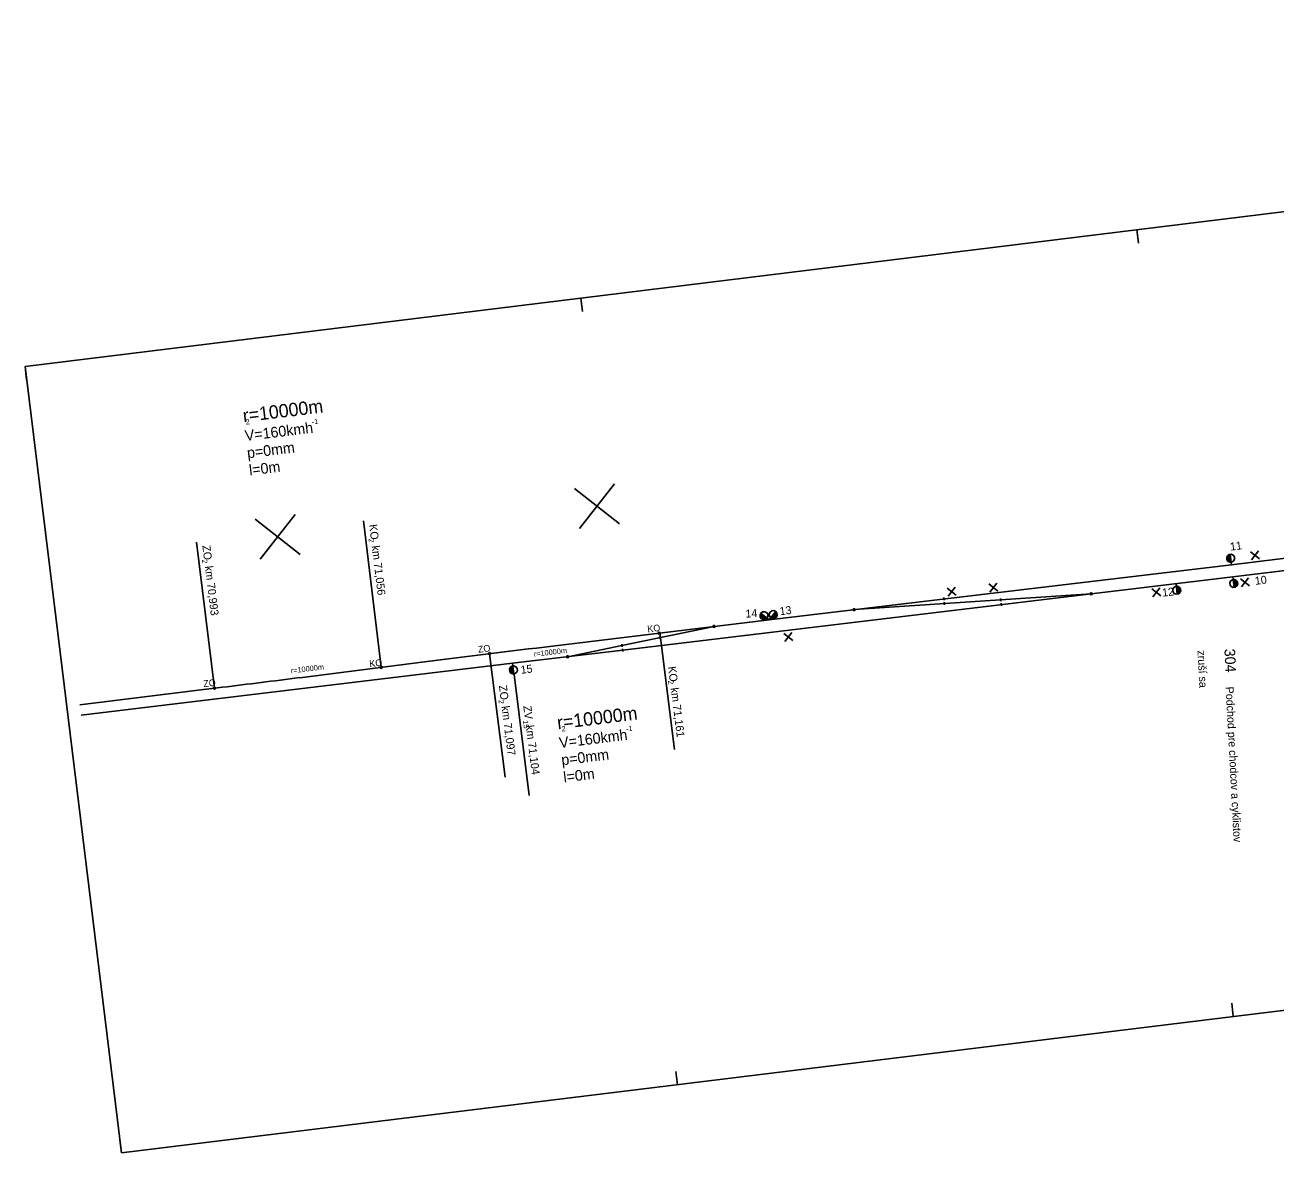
# Model space of a CAD drawing. Extents: x -559083 to -556962, y -1276579 to -1276028.
# Drawn here: x -559082.8 to -558613.7, y -1276578.6 to -1276155.9 of the extents above; entities that cross this region are included whole.
import ezdxf

# ---------------------------------------------------------------- set-up
doc = ezdxf.new("R2010")
doc.units = 0
for name, color, linetype in [('kolaj s', 7, 'Continuous'), ('popis 25', 7, 'Continuous'), ('popis 50', 7, 'Continuous'), ('ram vykresu', 7, 'Continuous'), ('stavby', 7, 'Continuous')]:
    doc.layers.add(name, color=color, linetype=linetype)

msp = doc.modelspace()

# ---------------------------------------------------------------- linework, layer by layer
at = {"layer": 'kolaj s'}
for p, q in [((-558630.38, -1276358.2), (-558589.1, -1276353.13)), ((-558630.38, -1276358.2), (-558727.08, -1276369.68)), ((-558629.83, -1276362.72), (-558588.54, -1276357.65)), ((-558858.64, -1276390.16), (-558629.83, -1276362.72)), ((-558727.08, -1276369.68), (-558803.72, -1276378.77)), ((-558771.92, -1276375), (-558682.98, -1276369.05)), ((-558738.22, -1276370.5), (-558738.1, -1276371.49)), ((-558738.16, -1276370.99), (-558738.16, -1276370.99)), ((-558716.97, -1276370.81), (-558716.84, -1276371.81)), ((-558682.98, -1276369.05), (-558682.98, -1276369.05)), ((-558771.92, -1276375), (-558771.92, -1276375)), ((-558738.06, -1276372.23), (-558737.94, -1276373.23)), ((-558738, -1276372.73), (-558738, -1276372.73)), ((-558716.91, -1276371.31), (-558716.91, -1276371.31)), ((-558716.79, -1276372.61), (-558716.67, -1276373.61)), ((-558716.73, -1276373.11), (-558716.73, -1276373.11)), ((-558803.72, -1276378.77), (-558885.02, -1276388.64)), ((-558824.36, -1276381.27), (-558858.92, -1276388.45)), ((-558844.95, -1276384.28), (-558845.07, -1276383.28)), ((-558845.02, -1276383.78), (-558845.02, -1276383.78)), ((-558845.01, -1276383.78), (-558845.01, -1276383.78)), ((-558844.63, -1276385.98), (-558844.83, -1276385)), ((-558824.36, -1276381.27), (-558824.36, -1276381.27)), ((-558879.29, -1276392.63), (-558858.92, -1276388.45)), ((-558859.02, -1276387.96), (-558858.82, -1276388.94)), ((-558858.92, -1276388.45), (-558858.92, -1276388.45)), ((-558858.7, -1276389.66), (-558858.58, -1276390.66)), ((-558844.73, -1276385.49), (-558844.73, -1276385.49)), ((-558979.74, -1276400.49), (-558932.96, -1276394.57)), ((-558908.55, -1276391.49), (-558908.55, -1276391.49)), ((-558899.94, -1276395.11), (-558858.64, -1276390.16)), ((-558879.29, -1276392.63), (-558879.29, -1276392.63)), ((-558858.64, -1276390.16), (-558858.64, -1276390.16)), ((-559061.68, -1276414.58), (-558899.94, -1276395.11)), ((-558949.2, -1276396.63), (-558949.2, -1276396.63)), ((-559008.73, -1276404.1), (-559062.16, -1276410.62)), ((-559011.74, -1276404.41), (-559011.74, -1276404.41))]:
    msp.add_line(p, q, dxfattribs=at)
for points in [[(-558682.98, -1276369.46), (-558683.32, -1276369.26), (-558683.32, -1276368.86), (-558682.98, -1276368.66), (-558682.63, -1276368.86), (-558682.63, -1276369.26), (-558682.98, -1276369.46)], [(-558771.52, -1276375), (-558771.71, -1276375.34), (-558772.11, -1276375.34), (-558772.32, -1276375), (-558772.11, -1276374.65), (-558771.71, -1276374.65), (-558771.52, -1276375)], [(-558844.97, -1276384.18), (-558845.33, -1276384.02), (-558845.38, -1276383.62), (-558845.06, -1276383.38), (-558844.69, -1276383.54), (-558844.65, -1276383.94), (-558844.97, -1276384.18)], [(-558824.76, -1276381.32), (-558824.6, -1276380.96), (-558824.21, -1276380.91), (-558823.96, -1276381.23), (-558824.12, -1276381.59), (-558824.52, -1276381.64), (-558824.76, -1276381.32)], [(-558908.6, -1276391.09), (-558908.23, -1276391.25), (-558908.18, -1276391.65), (-558908.5, -1276391.89), (-558908.87, -1276391.73), (-558908.92, -1276391.34), (-558908.6, -1276391.09)], [(-558878.89, -1276392.59), (-558879.05, -1276392.95), (-558879.44, -1276393), (-558879.68, -1276392.68), (-558879.53, -1276392.31), (-558879.13, -1276392.27), (-558878.89, -1276392.59)], [(-558949.25, -1276396.24), (-558948.88, -1276396.39), (-558948.83, -1276396.79), (-558949.15, -1276397.03), (-558949.52, -1276396.87), (-558949.57, -1276396.48), (-558949.25, -1276396.24)], [(-559011.79, -1276404.02), (-559011.42, -1276404.17), (-559011.37, -1276404.57), (-559011.69, -1276404.81), (-559012.06, -1276404.65), (-559012.11, -1276404.26), (-559011.79, -1276404.02)]]:
    msp.add_lwpolyline(points, dxfattribs=at)
for centre, start, end in [((-557680.08, -1286315.78), 96.920597, 97.197383), ((-560233.25, -1266479.36), 277.033672, 277.20105)]:
    msp.add_arc(centre, 10000, start, end, dxfattribs=at)
at = {"layer": 'popis 50'}
for p, q in [((-558861.67, -1276327.78), (-558874.83, -1276344.62)), ((-558859.83, -1276342.78), (-558876.68, -1276329.62)), ((-558979.59, -1276354.28), (-558996.44, -1276341.12)), ((-558981.44, -1276339.28), (-558994.59, -1276356.12)), ((-558955.89, -1276341.73), (-558949.21, -1276396.58)), ((-559018.41, -1276349.65), (-559011.73, -1276404.43)), ((-558630.38, -1276358.2), (-558630.86, -1276354.28)), ((-558619.88, -1276355.9), (-558623.25, -1276353.27)), ((-558620.25, -1276352.9), (-558622.88, -1276356.27)), ((-558630.38, -1276358.2), (-558630.38, -1276358.2)), ((-558718.04, -1276368.01), (-558721.41, -1276365.38)), ((-558718.41, -1276365.01), (-558721.04, -1276368.38)), ((-558651.18, -1276365.23), (-558651.18, -1276365.23)), ((-558651.18, -1276365.23), (-558650.7, -1276369.15)), ((-558629.83, -1276362.72), (-558629.83, -1276362.72)), ((-558629.83, -1276362.72), (-558629.35, -1276366.64)), ((-558623.57, -1276366.07), (-558626.94, -1276363.44)), ((-558623.94, -1276363.07), (-558626.57, -1276366.44)), ((-558733.6, -1276369.6), (-558736.97, -1276366.97)), ((-558733.97, -1276366.6), (-558736.6, -1276369.97)), ((-558656.93, -1276369.78), (-558660.3, -1276367.14)), ((-558657.3, -1276366.78), (-558659.93, -1276370.14)), ((-558803.72, -1276378.77), (-558803.72, -1276378.77)), ((-558839.22, -1276427.47), (-558844.76, -1276383.62)), ((-558794.89, -1276386.61), (-558798.26, -1276383.98)), ((-558795.26, -1276383.61), (-558797.89, -1276386.98)), ((-558902.72, -1276437.72), (-558908.55, -1276391.58)), ((-558899.94, -1276395.11), (-558899.94, -1276395.11)), ((-558899.94, -1276395.11), (-558899.45, -1276399.03)), ((-558893.67, -1276444.64), (-558899.4, -1276399.25))]:
    msp.add_line(p, q, dxfattribs=at)
for points in [[(-558631.26, -1276354.32), (-558630.47, -1276354.23), (-558629.74, -1276354.55), (-558629.3, -1276355.15), (-558629.2, -1276355.92), (-558629.51, -1276356.64), (-558630.11, -1276357.11), (-558630.91, -1276357.2), (-558631.61, -1276356.9), (-558632.08, -1276356.29), (-558632.18, -1276355.5), (-558631.87, -1276354.79), (-558631.26, -1276354.32), (-558631.48, -1276354.6), (-558630.98, -1276354.54), (-558630.95, -1276354.84), (-558631.79, -1276354.94), (-558631.95, -1276355.27), (-558630.91, -1276355.14), (-558630.87, -1276355.44), (-558632.02, -1276355.58), (-558631.98, -1276355.87), (-558630.84, -1276355.73), (-558630.8, -1276356.03), (-558631.94, -1276356.17), (-558631.76, -1276356.45), (-558630.76, -1276356.33), (-558630.73, -1276356.63), (-558631.57, -1276356.73), (-558631.19, -1276356.99), (-558630.69, -1276356.93)], [(-558650.3, -1276369.1), (-558651.1, -1276369.2), (-558651.82, -1276368.88), (-558652.27, -1276368.29), (-558652.36, -1276367.49), (-558652.06, -1276366.79), (-558651.45, -1276366.32), (-558650.66, -1276366.23), (-558649.95, -1276366.53), (-558649.48, -1276367.15), (-558649.39, -1276367.92), (-558649.69, -1276368.64), (-558650.3, -1276369.1), (-558650.08, -1276368.83), (-558650.58, -1276368.89), (-558650.62, -1276368.59), (-558649.77, -1276368.49), (-558649.66, -1276368.17), (-558650.65, -1276368.29), (-558650.69, -1276367.99), (-558649.55, -1276367.85), (-558649.58, -1276367.56), (-558650.73, -1276367.7), (-558650.76, -1276367.4), (-558649.62, -1276367.26), (-558649.81, -1276366.98), (-558650.8, -1276367.1), (-558650.84, -1276366.8), (-558650.04, -1276366.71), (-558650.43, -1276366.45), (-558650.87, -1276366.51)], [(-558628.95, -1276366.59), (-558629.74, -1276366.69), (-558630.47, -1276366.37), (-558630.91, -1276365.78), (-558631.01, -1276364.98), (-558630.71, -1276364.28), (-558630.1, -1276363.81), (-558629.3, -1276363.71), (-558628.6, -1276364.02), (-558628.13, -1276364.64), (-558628.04, -1276365.41), (-558628.34, -1276366.12), (-558628.95, -1276366.59), (-558628.73, -1276366.31), (-558629.23, -1276366.37), (-558629.27, -1276366.08), (-558628.42, -1276365.97), (-558628.31, -1276365.66), (-558629.3, -1276365.78), (-558629.34, -1276365.48), (-558628.2, -1276365.34), (-558628.23, -1276365.04), (-558629.37, -1276365.18), (-558629.41, -1276364.89), (-558628.27, -1276364.75), (-558628.45, -1276364.47), (-558629.45, -1276364.59), (-558629.48, -1276364.29), (-558628.69, -1276364.19), (-558629.07, -1276363.94), (-558629.52, -1276363.99)], [(-558804.49, -1276378.17), (-558804.18, -1276377.46), (-558804.28, -1276376.69), (-558804.74, -1276376.06), (-558805.46, -1276375.76), (-558806.23, -1276375.85), (-558806.85, -1276376.32), (-558807.16, -1276377.04), (-558807.06, -1276377.81), (-558806.59, -1276378.43), (-558805.88, -1276378.73), (-558805.11, -1276378.64), (-558804.49, -1276378.17), (-558804.86, -1276378.05), (-558805.26, -1276378.56), (-558805.65, -1276378.6), (-558805.13, -1276377.94), (-558805.36, -1276377.71), (-558805.96, -1276378.54), (-558806.28, -1276378.43), (-558805.58, -1276377.54), (-558805.81, -1276377.36), (-558806.55, -1276378.26), (-558806.73, -1276378.03), (-558806.04, -1276377.14), (-558806.26, -1276376.97), (-558806.87, -1276377.75), (-558806.97, -1276377.35), (-558806.53, -1276376.8), (-558806.76, -1276376.57), (-558806.98, -1276376.85)], [(-558806.84, -1276376.33), (-558803.72, -1276378.77), (-558801.28, -1276375.65)], [(-558801.27, -1276375.64), (-558801.99, -1276375.33), (-558802.76, -1276375.43), (-558803.41, -1276375.93), (-558803.68, -1276376.61), (-558803.59, -1276377.38), (-558803.12, -1276378), (-558802.4, -1276378.3), (-558801.63, -1276378.21), (-558801.04, -1276377.78), (-558800.71, -1276377.03), (-558800.8, -1276376.26), (-558801.27, -1276375.64), (-558801.34, -1276376.01), (-558800.95, -1276376.31), (-558800.89, -1276376.76), (-558801.51, -1276376.28), (-558801.68, -1276376.51), (-558800.9, -1276377.11), (-558801.01, -1276377.43), (-558801.9, -1276376.73), (-558802.07, -1276377.01), (-558801.19, -1276377.65), (-558801.41, -1276377.88), (-558802.25, -1276377.23), (-558802.42, -1276377.45), (-558801.64, -1276378.06), (-558802.09, -1276378.12), (-558802.64, -1276377.68), (-558802.82, -1276377.9), (-558802.48, -1276378.17)], [(-558899.85, -1276399.08), (-558899.06, -1276398.98), (-558898.45, -1276398.51), (-558898.14, -1276397.81), (-558898.24, -1276397.02), (-558898.71, -1276396.41), (-558899.45, -1276396.1), (-558900.19, -1276396.2), (-558900.81, -1276396.67), (-558901.12, -1276397.37), (-558901.02, -1276398.16), (-558900.56, -1276398.77), (-558899.85, -1276399.08), (-558900.13, -1276398.86), (-558899.63, -1276398.8), (-558899.67, -1276398.5), (-558900.51, -1276398.6), (-558900.75, -1276398.33), (-558899.71, -1276398.2), (-558899.74, -1276397.9), (-558900.89, -1276398.04), (-558900.92, -1276397.75), (-558899.78, -1276397.61), (-558899.82, -1276397.31), (-558900.96, -1276397.45), (-558900.85, -1276397.13), (-558899.85, -1276397.01), (-558899.89, -1276396.71), (-558900.73, -1276396.82), (-558900.37, -1276396.47), (-558899.93, -1276396.42)]]:
    msp.add_lwpolyline(points, dxfattribs=at)
at = {"layer": 'ram vykresu'}
for p, q in [((-559082.77, -1276283.84), (-558040.59, -1276155.88)), ((-558665.29, -1276237.62), (-558665.9, -1276232.66)), ((-558873.72, -1276263.21), (-558874.33, -1276258.25)), ((-559046.57, -1276578.63), (-559082.77, -1276283.84)), ((-559082.16, -1276288.8), (-559082.77, -1276283.84)), ((-558004.4, -1276450.67), (-559046.57, -1276578.63)), ((-558629.7, -1276527.44), (-558630.31, -1276522.48)), ((-558838.14, -1276553.04), (-558838.75, -1276548.07)), ((-559046.57, -1276578.63), (-559047.18, -1276573.67))]:
    msp.add_line(p, q, dxfattribs=at)

# ---------------------------------------------------------------- texts
at = {"layer": 'popis 25'}
for p in [(-558891.87, -1276392.7), (-558983, -1276398.91)]:
    msp.add_text('r=10000m', height=2, rotation=7, dxfattribs=at).set_placement(p)
at = {"layer": 'popis 50'}
for s, height, rotation, p in [('r=10000m', 5, 7, (-559000.81, -1276304.78)), ('V=160kmh', 4, 7, (-559000.08, -1276311.81)), ('2', 2, 7, (-558999.92, -1276305.66)), ('-1', 2, 7, (-558975.13, -1276305.6)), ('p=0mm', 4, 7, (-558999.29, -1276318.26)), ('l=0m', 4, 7, (-558998.5, -1276324.71)), ('KO  km 71,056', 3, 276.9472, (-558953.76, -1276343.18)), ('ZO  km 70,993', 3, 276.9472, (-559016.29, -1276351.03)), ('2', 2, 276.9472, (-558953.96, -1276348.41)), ('11', 3, 7, (-558630.74, -1276352.89)), ('2', 2, 276.9472, (-559016.48, -1276356.25)), ('10', 3, 7, (-558621.43, -1276365.7)), ('12', 3, 7, (-558656.2, -1276370.15)), ('14', 3, 3.9202, (-558812.52, -1276378.03)), ('13', 3, 7, (-558799.63, -1276377.11)), ('KO', 2.5, 7, (-558849.25, -1276383.56)), ('ZO', 2.5, 7, (-558912.77, -1276391.16)), ('KO', 2.5, 7, (-558953.49, -1276396.58)), ('15', 3, 7, (-558896.75, -1276399.06)), ('KO  km 71,161', 3, 277.1974, (-558841.68, -1276396.43)), ('ZO', 2.5, 7, (-559015.75, -1276404.06)), ('ZO  km 71,097', 3, 277.1974, (-558905.09, -1276403.49)), ('2', 2, 277.1974, (-558841.7, -1276401.59)), ('2', 2, 277.1974, (-558905.24, -1276408.91)), ('ZV  km 71,104', 3, 277.1974, (-558895.94, -1276411.16)), ('r=10000m', 5, 7, (-558882.95, -1276419.86)), ('15', 2, 277.1974, (-558896.09, -1276416.58)), ('V=160kmh', 4, 7, (-558882.23, -1276426.89)), ('2', 2, 7, (-558881.46, -1276420.7)), ('-1', 2, 7, (-558857.28, -1276420.68)), ('p=0mm', 4, 7, (-558881.44, -1276433.34)), ('l=0m', 4, 7, (-558880.65, -1276439.8))]:
    msp.add_text(s, height=height, rotation=rotation, dxfattribs=at).set_placement(p)
at = {"layer": 'stavby'}
for s, height, p in [('304', 4, (-558633.05, -1276389.73)), ('zruší sa', 3, (-558643.13, -1276390.31)), ('Podchod pre chodcov a cyklistov', 3, (-558632.6, -1276403.91))]:
    msp.add_text(s, height=height, rotation=273, dxfattribs=at).set_placement(p)

doc.saveas('drawing.dxf')
